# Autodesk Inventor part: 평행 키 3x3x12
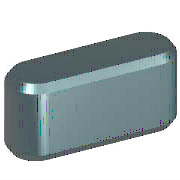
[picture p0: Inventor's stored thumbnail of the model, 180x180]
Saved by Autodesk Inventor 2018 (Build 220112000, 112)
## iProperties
IsCustomPart: 1
Created: 2012-02
Part Number: 평행 키 3x3x12
Material: 강철, 연강
Description: 평행 키
Document SubType Name: Modeling
Standard: JIS B 1301
Designer: mdu-01
Standards Organization: JIS
Language: ko-KR
Size Designation: 3x3x12
Categories: <MemberInstance><Categories><Category DisplayName="샤프트 부품" InternalName="7f7aeb1f-a693-4053-b835-cee3144e0d98" Mnemonic="SHFT"><Category DisplayName="키" Interna
Density: 1 g/cm^3
Appearance: 기본값(1)
Author: mdu-01
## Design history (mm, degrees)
workplane "Work Plane1"
workplane "Work Plane2"
sketch "스케치1"
  geometry: L1 (1.5, 1.5)-(10.5, 1.5); L2 (10.5, -1.5)-(1.5, -1.5); L3 (0, 9.4)-(0, -7.4) reference; L4 (-5, 0)-(30, 0) reference; L5 (12, 0)-(12, 7); A1 r 1.5 centre (1.5, 0) between (1.5, 1.5) and (1.5, -1.5); A2 r 1.5 centre (10.5, 0) between (10.5, -1.5) and (10.5, 1.5)
  constraints: 6 end point, 5 point on circle, 4 tangent, 3 point on line, 2 centre point, 1 horizontal, 1 parallel, 1 perpendicular
  dimensions: "d0" = 1.5 radius of A1 (= 0.5 x PB); "d13" = 1.5 radius of A2 (= 0.5 x PB); "d14" = 12 distance between parallel lines of L5 L3 (= NLG)
extrude "본체1" new body sketch "스케치1" taper "d3" = 0 deg; stored distance "d4" = 10
workplane "Work Plane3"
body "Solid1"
chamfer "모따기1" distance "d8" = 0.25 (= PHH); stored, may be unused: second distance "d9" = 0.25 (= PHH), angle "d15" = 45 deg
other parameters: "d1" = -1.8 (= -PNT), "d2" = 1.2 (= PH - PNT), "NLG" = 12 [user parameter; used in 3 equation terms], "PB" = 3 [user parameter; used in 2 equation terms], "PNT" = 1.8 [user parameter; used in 2 equation terms], "PH" = 3 [user parameter; used in 1 equation term], "PHH" = 0.25 [user parameter; used in 2 equation terms], "d10" = 0, "d16" = 0, "d17" = 0, "d18" = 0, "WDMIN" = 8 [user parameter], "PLB2" = 12 (= NLG) [user parameter], "PLB1" = 12 (= NLG) [user parameter], "RR" = 0.08 [user parameter], "PUEB" = 1.4 [user parameter]
